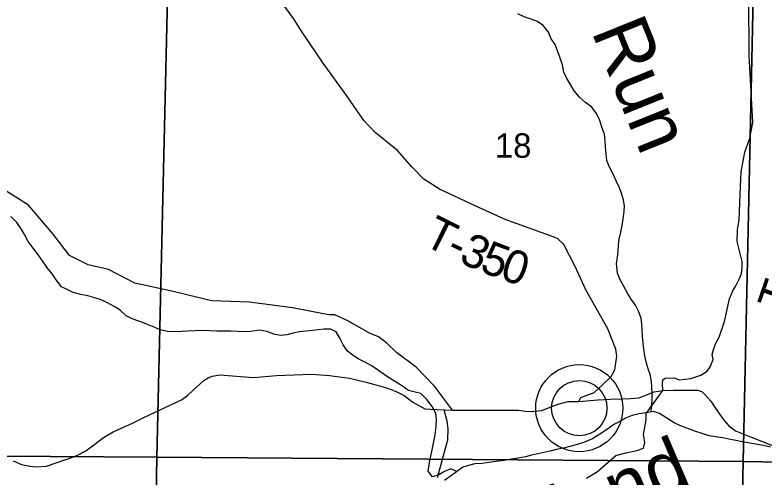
# Model space of a CAD drawing. Extents: x 0 to 34, y 0 to 22.
# Drawn here: x 3.273 to 4.552, y 18.088 to 18.878 of the extents above; entities that cross this region are included whole.
import ezdxf

# ---------------------------------------------------------------- set-up
doc = ezdxf.new("R2010")
doc.units = 0
for name, color, linetype in [('GM_X_County_Road', 7, 'Continuous'), ('GM_X_Minor_River', 7, 'Continuous'), ('GM_X_Minor_River_Text', 7, 'Continuous'), ('GM_X_Section', 7, 'Continuous'), ('GM_X_Section_Text', 7, 'Continuous'), ('GM_X_Township_Road', 7, 'Continuous'), ('GM_X_Township_Road_Text', 7, 'Continuous'), ('GM_X_Unincorporated', 7, 'Continuous'), ('GM_X_Unincorporated_Location', 7, 'Continuous')]:
    doc.layers.add(name, color=color, linetype=linetype)

msp = doc.modelspace()

# ---------------------------------------------------------------- linework, layer by layer
at = {"layer": 'GM_X_County_Road'}
for p, q in [((3.5775, 18.2366), (3.5956, 18.2532)), ((3.5956, 18.2532), (3.6027, 18.2576)), ((3.6027, 18.2576), (3.6094, 18.2609)), ((3.6094, 18.2609), (3.6226, 18.2629)), ((3.6226, 18.2629), (3.6801, 18.2585)), ((3.6801, 18.2585), (3.7197, 18.262)), ((3.7197, 18.262), (3.78, 18.2638)), ((3.78, 18.2638), (3.8103, 18.2619)), ((3.8103, 18.2619), (3.844, 18.257)), ((3.844, 18.257), (3.8725, 18.2504)), ((3.8725, 18.2504), (3.9015, 18.2423)), ((3.9015, 18.2423), (3.9152, 18.2378)), ((3.5571, 18.2203), (3.5676, 18.2275)), ((3.5676, 18.2275), (3.5775, 18.2366)), ((3.9152, 18.2378), (3.926, 18.2332)), ((3.926, 18.2332), (3.9378, 18.2276)), ((3.9378, 18.2276), (3.9522, 18.2163)), ((4.3389, 18.2238), (4.3516, 18.2287)), ((4.3516, 18.2287), (4.3644, 18.234)), ((4.3644, 18.234), (4.3793, 18.236)), ((4.3793, 18.236), (4.3975, 18.2368)), ((4.3975, 18.2368), (4.4395, 18.2365)), ((4.4395, 18.2365), (4.4464, 18.2337)), ((4.4464, 18.2337), (4.451, 18.2295)), ((4.451, 18.2295), (4.4613, 18.2179)), ((3.4943, 18.1906), (3.5571, 18.2203)), ((3.9522, 18.2163), (3.9726, 18.2051)), ((4.2007, 18.2129), (4.2178, 18.2175)), ((4.2178, 18.2175), (4.2357, 18.2174)), ((4.2357, 18.2174), (4.2681, 18.2202)), ((4.2681, 18.2202), (4.2897, 18.2213)), ((4.2897, 18.2213), (4.3089, 18.222)), ((4.3089, 18.222), (4.3239, 18.2223)), ((4.3239, 18.2223), (4.3389, 18.2238)), ((4.4613, 18.2179), (4.4735, 18.1991)), ((3.9726, 18.2051), (3.9822, 18.2041)), ((3.9822, 18.2041), (4.0058, 18.2033)), ((4.0058, 18.2033), (4.0199, 18.2026)), ((4.0199, 18.2026), (4.1326, 18.2027)), ((4.1326, 18.2027), (4.1441, 18.2008)), ((4.155, 18.2004), (4.1721, 18.2019)), ((4.1721, 18.2019), (4.2007, 18.2129)), ((3.4738, 18.1802), (3.4943, 18.1906)), ((4.1441, 18.2008), (4.155, 18.2004)), ((4.4735, 18.1991), (4.484, 18.1851)), ((3.4409, 18.1653), (3.4738, 18.1802)), ((4.484, 18.1851), (4.4919, 18.176)), ((4.4919, 18.176), (4.5034, 18.1673)), ((3.4242, 18.1561), (3.4409, 18.1653)), ((4.5034, 18.1673), (4.5292, 18.1568)), ((3.4069, 18.1429), (3.4242, 18.1561)), ((4.5292, 18.1568), (4.5694, 18.1412)), ((3.3939, 18.1333), (3.4069, 18.1429)), ((3.3731, 18.1226), (3.3795, 18.1254)), ((3.3795, 18.1254), (3.3939, 18.1333)), ((3.2697, 18.1161), (3.2843, 18.11)), ((3.3267, 18.1069), (3.3731, 18.1226)), ((3.2843, 18.11), (3.2991, 18.1066)), ((3.2991, 18.1066), (3.309, 18.1057)), ((3.309, 18.1057), (3.3267, 18.1069))]:
    msp.add_line(p, q, dxfattribs=at)
at = {"layer": 'GM_X_Minor_River'}
for p, q in [((4.1424, 18.8745), (4.1316, 18.8794)), ((4.1528, 18.871), (4.1424, 18.8745)), ((4.1651, 18.8664), (4.1528, 18.871)), ((4.1756, 18.8588), (4.1651, 18.8664)), ((4.1839, 18.8484), (4.1756, 18.8588)), ((4.1888, 18.8371), (4.1839, 18.8484)), ((4.1952, 18.827), (4.1888, 18.8371)), ((4.1993, 18.8165), (4.1952, 18.827)), ((4.2031, 18.8056), (4.1993, 18.8165)), ((4.2077, 18.7924), (4.2031, 18.8056)), ((4.21, 18.78), (4.2077, 18.7924)), ((4.2148, 18.7702), (4.21, 18.78)), ((4.2213, 18.7586), (4.2148, 18.7702)), ((4.2281, 18.7478), (4.2213, 18.7586)), ((4.2368, 18.7374), (4.2281, 18.7478)), ((4.2469, 18.7283), (4.2368, 18.7374)), ((4.2578, 18.7202), (4.2469, 18.7283)), ((4.2662, 18.7091), (4.2578, 18.7202)), ((4.2715, 18.6975), (4.2662, 18.7091)), ((4.2749, 18.6862), (4.2715, 18.6975)), ((4.2798, 18.6741), (4.2749, 18.6862)), ((4.2809, 18.6624), (4.2798, 18.6741)), ((4.2816, 18.6521), (4.2809, 18.6624)), ((4.2824, 18.6407), (4.2816, 18.6521)), ((4.2835, 18.629), (4.2824, 18.6407)), ((4.2876, 18.6185), (4.2835, 18.629)), ((4.2941, 18.6069), (4.2876, 18.6185)), ((4.2998, 18.5945), (4.2941, 18.6069)), ((4.3051, 18.5825), (4.2998, 18.5945)), ((4.3092, 18.5716), (4.3051, 18.5825)), ((4.3118, 18.5614), (4.3092, 18.5716)), ((4.3137, 18.5516), (4.3118, 18.5614)), ((4.3132, 18.542), (4.3137, 18.5516)), ((4.3117, 18.5291), (4.3132, 18.542)), ((3.2762, 18.5229), (3.2657, 18.5332)), ((3.2834, 18.5125), (3.2762, 18.5229)), ((4.3098, 18.518), (4.3117, 18.5291)), ((3.289, 18.5024), (3.2834, 18.5125)), ((4.3075, 18.5065), (4.3098, 18.518)), ((3.2955, 18.4908), (3.289, 18.5024)), ((4.3048, 18.4946), (4.3075, 18.5065)), ((3.3038, 18.4793), (3.2955, 18.4908)), ((4.3031, 18.474), (4.3036, 18.4851)), ((4.3036, 18.4851), (4.3048, 18.4946)), ((3.3129, 18.4674), (3.3038, 18.4793)), ((4.3016, 18.4633), (4.3031, 18.474)), ((3.3213, 18.4558), (3.3129, 18.4674)), ((4.3004, 18.453), (4.3016, 18.4633)), ((3.3285, 18.445), (3.3213, 18.4558)), ((3.3364, 18.4354), (3.3285, 18.445)), ((4.3017, 18.4363), (4.3004, 18.453)), ((3.3435, 18.4249), (3.3364, 18.4354)), ((4.3062, 18.425), (4.3017, 18.4363)), ((3.3523, 18.4134), (3.3435, 18.4249)), ((4.3122, 18.415), (4.3062, 18.425)), ((3.3623, 18.4084), (3.3523, 18.4134)), ((3.3723, 18.4038), (3.3623, 18.4084)), ((4.3191, 18.4022), (4.3122, 18.415)), ((3.3854, 18.4004), (3.3723, 18.4038)), ((3.3976, 18.3981), (3.3854, 18.4004)), ((3.4095, 18.3943), (3.3976, 18.3981)), ((3.4199, 18.3908), (3.4095, 18.3943)), ((4.3251, 18.3921), (4.3191, 18.4022)), ((3.4311, 18.3858), (3.4199, 18.3908)), ((3.4423, 18.3797), (3.4311, 18.3858)), ((4.3323, 18.3817), (4.3251, 18.3921)), ((4.3379, 18.3716), (4.3323, 18.3817)), ((3.4524, 18.3732), (3.4423, 18.3797)), ((3.4629, 18.3636), (3.4524, 18.3732)), ((4.3421, 18.3596), (4.3379, 18.3716)), ((3.4733, 18.3586), (3.4629, 18.3636)), ((3.4845, 18.3548), (3.4733, 18.3586)), ((3.4964, 18.3502), (3.4845, 18.3548)), ((4.3431, 18.3493), (4.3421, 18.3596)), ((3.5107, 18.3446), (3.4964, 18.3502)), ((3.5211, 18.3396), (3.5107, 18.3446)), ((4.3442, 18.3391), (4.3431, 18.3493)), ((3.5333, 18.3369), (3.5211, 18.3396)), ((3.547, 18.3362), (3.5333, 18.3369)), ((3.5584, 18.3369), (3.547, 18.3362)), ((3.5679, 18.3376), (3.5584, 18.3369)), ((3.593, 18.3384), (3.5679, 18.3376)), ((3.6055, 18.338), (3.593, 18.3384)), ((3.6177, 18.3376), (3.6055, 18.338)), ((3.6302, 18.3377), (3.6177, 18.3376)), ((3.6417, 18.3376), (3.6302, 18.3377)), ((3.6527, 18.3372), (3.6417, 18.3376)), ((3.6649, 18.3365), (3.6527, 18.3372)), ((3.6755, 18.3372), (3.6649, 18.3365)), ((3.6906, 18.3392), (3.6755, 18.3372)), ((3.7029, 18.3369), (3.6906, 18.3392)), ((3.7167, 18.332), (3.7029, 18.3369)), ((3.7267, 18.33), (3.7167, 18.332)), ((3.7373, 18.3311), (3.7267, 18.33)), ((3.7478, 18.3341), (3.7373, 18.3311)), ((3.7588, 18.3363), (3.7478, 18.3341)), ((3.7808, 18.3386), (3.7588, 18.3363)), ((3.7906, 18.34), (3.7808, 18.3386)), ((3.8005, 18.3411), (3.7906, 18.34)), ((3.8119, 18.3407), (3.8005, 18.3411)), ((3.8215, 18.3364), (3.8119, 18.3407)), ((3.8276, 18.3256), (3.8215, 18.3364)), ((4.3445, 18.3288), (4.3442, 18.3391)), ((3.8332, 18.3139), (3.8276, 18.3256)), ((4.3457, 18.3171), (4.3445, 18.3288)), ((4.3468, 18.3065), (4.3457, 18.3171)), ((3.8404, 18.3039), (3.8332, 18.3139)), ((3.8505, 18.2958), (3.8404, 18.3039)), ((4.3486, 18.2955), (4.3468, 18.3065)), ((3.8602, 18.2897), (3.8505, 18.2958)), ((4.3508, 18.2853), (4.3486, 18.2955)), ((3.8714, 18.2839), (3.8602, 18.2897)), ((3.8823, 18.2782), (3.8714, 18.2839)), ((3.8959, 18.2687), (3.8823, 18.2782)), ((4.3534, 18.2751), (4.3508, 18.2853)), ((3.9091, 18.2593), (3.8959, 18.2687)), ((4.3576, 18.2634), (4.3534, 18.2751)), ((3.9347, 18.2433), (3.9091, 18.2593)), ((4.3599, 18.2517), (4.3576, 18.2634)), ((3.9451, 18.2364), (3.9347, 18.2433)), ((4.3606, 18.2415), (4.3599, 18.2517)), ((4.3609, 18.2316), (4.3606, 18.2415)), ((3.9563, 18.2333), (3.9451, 18.2364)), ((3.9658, 18.231), (3.9563, 18.2333)), ((3.976, 18.221), (3.9658, 18.231)), ((4.3608, 18.2213), (4.3609, 18.2316)), ((3.9852, 18.2087), (3.976, 18.221)), ((4.3604, 18.2095), (4.3608, 18.2213)), ((3.9916, 18.1968), (3.9852, 18.2087)), ((4.3586, 18.1994), (4.3604, 18.2095)), ((3.9927, 18.1862), (3.9916, 18.1968)), ((4.3154, 18.1887), (4.3057, 18.1834)), ((4.3271, 18.1936), (4.3154, 18.1887)), ((4.3391, 18.1963), (4.3271, 18.1936)), ((4.3501, 18.1981), (4.3391, 18.1963)), ((4.3634, 18.2001), (4.3501, 18.1981)), ((4.3737, 18.1966), (4.3634, 18.2001)), ((4.3861, 18.189), (4.3737, 18.1966)), ((4.3986, 18.181), (4.3861, 18.189)), ((3.9919, 18.1755), (3.9927, 18.1862)), ((4.2956, 18.1778), (4.2833, 18.169)), ((4.3057, 18.1834), (4.2956, 18.1778)), ((4.4082, 18.1764), (4.3986, 18.181)), ((4.4205, 18.1718), (4.4082, 18.1764)), ((3.9891, 18.1545), (3.9911, 18.1644)), ((3.9911, 18.1644), (3.9919, 18.1755)), ((4.2833, 18.169), (4.2714, 18.1614)), ((4.4336, 18.1665), (4.4205, 18.1718)), ((4.4482, 18.162), (4.4336, 18.1665)), ((3.9868, 18.1434), (3.9891, 18.1545)), ((4.2591, 18.1534), (4.2452, 18.1477)), ((4.2714, 18.1614), (4.2591, 18.1534)), ((4.4585, 18.1589), (4.4482, 18.162)), ((4.4689, 18.157), (4.4585, 18.1589)), ((4.4815, 18.1551), (4.4689, 18.157)), ((4.4922, 18.1531), (4.4815, 18.1551)), ((4.504, 18.1508), (4.4922, 18.1531)), ((4.5148, 18.1485), (4.504, 18.1508)), ((3.9849, 18.1319), (3.9868, 18.1434)), ((4.2094, 18.1378), (4.1973, 18.1351)), ((4.2203, 18.1404), (4.2094, 18.1378)), ((4.2313, 18.1434), (4.2203, 18.1404)), ((4.2452, 18.1477), (4.2313, 18.1434)), ((4.5247, 18.1465), (4.5148, 18.1485)), ((4.5373, 18.1443), (4.5247, 18.1465)), ((4.5511, 18.142), (4.5373, 18.1443)), ((4.563, 18.1394), (4.5511, 18.142)), ((3.9825, 18.1215), (3.9849, 18.1319)), ((4.1547, 18.1254), (4.1449, 18.1228)), ((4.1656, 18.128), (4.1547, 18.1254)), ((4.186, 18.1325), (4.1656, 18.128)), ((4.1973, 18.1351), (4.186, 18.1325)), ((3.9802, 18.11), (3.9825, 18.1215)), ((4.0703, 18.1117), (4.0582, 18.1106)), ((4.0828, 18.1129), (4.0703, 18.1117)), ((4.0945, 18.1148), (4.0828, 18.1129)), ((4.1082, 18.1167), (4.0945, 18.1148)), ((4.1206, 18.119), (4.1082, 18.1167)), ((4.1324, 18.1205), (4.1206, 18.119)), ((4.1449, 18.1228), (4.1324, 18.1205)), ((3.9783, 18.0986), (3.9802, 18.11)), ((4.0174, 18.1025), (4.0065, 18.0975)), ((4.0273, 18.0976), (4.0174, 18.1025)), ((4.0378, 18.105), (4.027, 18.0974)), ((4.0476, 18.108), (4.0378, 18.105)), ((4.0582, 18.1106), (4.0476, 18.108)), ((3.9858, 18.0885), (3.9783, 18.0986)), ((3.9968, 18.0923), (3.9858, 18.0885)), ((4.0065, 18.0975), (3.9968, 18.0923)), ((4.0162, 18.0891), (4.0066, 18.0823)), ((4.027, 18.0974), (4.0162, 18.0891))]:
    msp.add_line(p, q, dxfattribs=at)
at = {"layer": 'GM_X_Section'}
for p, q in [((3.5387, 19.1524), (3.5154, 18.1224)), ((3.5154, 18.1224), (3.5387, 19.1524)), ((4.5388, 19.1444), (4.5166, 18.1148)), ((4.5166, 18.1148), (4.5388, 19.1444)), ((3.5154, 18.1224), (2.5107, 18.1291)), ((2.5107, 18.1291), (3.5154, 18.1224)), ((3.5154, 18.1224), (3.4934, 17.1171)), ((3.4934, 17.1171), (3.5154, 18.1224)), ((4.5166, 18.1148), (3.5154, 18.1224)), ((3.5154, 18.1224), (4.5166, 18.1148)), ((4.5166, 18.1148), (4.4928, 17.1099)), ((4.4928, 17.1099), (4.5166, 18.1148)), ((5.5198, 18.1024), (4.5166, 18.1148)), ((4.5166, 18.1148), (5.5198, 18.1024))]:
    msp.add_line(p, q, dxfattribs=at)
at = {"layer": 'GM_X_Township_Road'}
for p, q in [((4.5268, 18.8092), (4.5262, 18.9174)), ((3.7486, 18.8714), (3.7288, 18.8988)), ((3.7645, 18.8465), (3.7486, 18.8714)), ((3.7994, 18.7953), (3.7645, 18.8465)), ((4.5327, 18.6939), (4.5268, 18.8092)), ((3.8396, 18.7396), (3.7994, 18.7953)), ((3.8689, 18.6973), (3.8396, 18.7396)), ((3.8879, 18.6771), (3.8689, 18.6973)), ((4.5276, 18.6674), (4.5327, 18.6939)), ((3.9259, 18.6462), (3.8879, 18.6771)), ((4.5193, 18.6431), (4.5276, 18.6674)), ((3.9509, 18.618), (3.9259, 18.6462)), ((4.5132, 18.6095), (4.5193, 18.6431)), ((3.9711, 18.5969), (3.9509, 18.618)), ((4.5117, 18.5848), (4.5132, 18.6095)), ((3.998, 18.5798), (3.9711, 18.5969)), ((3.2961, 18.5526), (3.2459, 18.5838)), ((4.0586, 18.5514), (3.998, 18.5798)), ((4.511, 18.5565), (4.5117, 18.5848)), ((3.338, 18.5031), (3.2961, 18.5526)), ((4.1098, 18.528), (4.0586, 18.5514)), ((4.5096, 18.5279), (4.511, 18.5565)), ((4.1918, 18.4988), (4.1098, 18.528)), ((4.5066, 18.5113), (4.5096, 18.5279)), ((4.5062, 18.4909), (4.5066, 18.5113)), ((3.366, 18.4668), (3.338, 18.5031)), ((4.1994, 18.4957), (4.1918, 18.4988)), ((4.2099, 18.4854), (4.1994, 18.4957)), ((4.2293, 18.448), (4.2099, 18.4854)), ((4.5145, 18.4565), (4.5062, 18.4909)), ((3.3981, 18.4507), (3.366, 18.4668)), ((3.4329, 18.4427), (3.3981, 18.4507)), ((4.248, 18.4081), (4.2293, 18.448)), ((4.5137, 18.4362), (4.5145, 18.4459)), ((4.5145, 18.4459), (4.5145, 18.4565)), ((3.4778, 18.4193), (3.4329, 18.4427)), ((4.51, 18.4275), (4.5137, 18.4362)), ((3.5431, 18.4051), (3.4778, 18.4193)), ((4.5038, 18.4148), (4.51, 18.4275)), ((4.2856, 18.3417), (4.248, 18.4081)), ((4.4932, 18.3927), (4.4987, 18.4065)), ((4.4987, 18.4065), (4.5038, 18.4148)), ((3.6085, 18.3894), (3.5431, 18.4051)), ((3.6736, 18.3873), (3.6085, 18.3894)), ((3.7467, 18.3772), (3.6736, 18.3873)), ((4.4843, 18.3542), (4.4932, 18.3927)), ((3.8087, 18.3652), (3.7467, 18.3772)), ((3.819, 18.3653), (3.8087, 18.3652)), ((3.8412, 18.3549), (3.819, 18.3653)), ((3.8785, 18.3341), (3.8412, 18.3549)), ((4.4752, 18.3275), (4.4843, 18.3542)), ((3.8935, 18.3278), (3.8785, 18.3341)), ((4.2987, 18.3066), (4.2856, 18.3417)), ((3.9085, 18.3166), (3.8935, 18.3278)), ((3.9244, 18.3011), (3.9085, 18.3166)), ((4.4662, 18.3076), (4.4697, 18.3172)), ((4.4697, 18.3172), (4.4724, 18.3223)), ((4.4724, 18.3223), (4.4752, 18.3275)), ((4.3005, 18.2947), (4.2987, 18.3066)), ((4.4634, 18.2975), (4.4652, 18.3039)), ((4.4652, 18.3039), (4.4662, 18.3076)), ((3.9579, 18.2762), (3.9244, 18.3011)), ((4.2973, 18.2717), (4.3005, 18.2947)), ((4.4652, 18.2892), (4.4634, 18.2975)), ((4.4601, 18.2768), (4.4652, 18.2892)), ((3.9894, 18.2433), (3.9579, 18.2762)), ((4.2911, 18.2603), (4.2973, 18.2717)), ((4.4439, 18.2622), (4.4547, 18.2693)), ((4.4547, 18.2693), (4.4601, 18.2768)), ((4.2757, 18.2454), (4.2911, 18.2603)), ((4.3786, 18.2483), (4.3794, 18.2541)), ((4.3794, 18.2541), (4.3832, 18.2574)), ((4.3832, 18.2574), (4.398, 18.258)), ((4.398, 18.258), (4.4079, 18.2545)), ((4.4079, 18.2545), (4.4271, 18.2566)), ((4.4271, 18.2566), (4.4439, 18.2622)), ((4.0199, 18.2026), (3.9894, 18.2433)), ((4.2619, 18.2327), (4.2757, 18.2454)), ((4.3793, 18.236), (4.3786, 18.2483)), ((4.2392, 18.2242), (4.2619, 18.2327)), ((4.351, 18.1968), (4.3737, 18.2283)), ((4.3737, 18.2283), (4.3793, 18.236)), ((4.2357, 18.2174), (4.2392, 18.2242)), ((4.0058, 18.2033), (4.0199, 18.2026)), ((4.0111, 18.1837), (4.0058, 18.2033)), ((4.3506, 18.1861), (4.351, 18.1968)), ((4.0125, 18.1707), (4.0111, 18.1837)), ((4.3463, 18.1607), (4.3506, 18.1861)), ((4.0121, 18.1516), (4.0125, 18.1707)), ((3.9943, 18.0877), (4.0121, 18.1516)), ((4.3484, 18.1471), (4.3463, 18.1607)), ((4.335, 18.1337), (4.3461, 18.1378)), ((4.3461, 18.1378), (4.3484, 18.1471)), ((4.286, 18.1139), (4.2989, 18.1253)), ((4.2989, 18.1253), (4.316, 18.1297)), ((4.316, 18.1297), (4.335, 18.1337)), ((4.2675, 18.0977), (4.286, 18.1139)), ((4.249, 18.0865), (4.2675, 18.0977))]:
    msp.add_line(p, q, dxfattribs=at)
at = {"layer": 'GM_X_Unincorporated'}
for radius in [0.0744, 0.0472]:
    msp.add_circle((4.2366, 18.206), radius, dxfattribs=at)
at = {"layer": 'GM_X_Unincorporated_Location'}
msp.add_line((4.2366, 18.206), (4.2366, 18.206), dxfattribs=at)

# ---------------------------------------------------------------- texts
at = {"layer": 'GM_X_Minor_River_Text'}
for s, height, rotation, p in [('Run', 0.0947, 291.9594, (4.2566, 18.85)), ('Island', 0.09472, 23.1154, (4.1229, 17.9398))]:
    msp.add_text(s, height=height, rotation=rotation, dxfattribs=at).set_placement(p)
at = {"layer": 'GM_X_Section_Text'}
msp.add_text('18', height=0.04186, rotation=0, dxfattribs=at).set_placement((4.0926, 18.6336))
at = {"layer": 'GM_X_Township_Road_Text'}
for s, rotation, p in [('T', 333.5749, (3.9677, 18.4861)), ('3', 335.8451, (4.029, 18.4561)), ('-', 334.526, (4.0066, 18.4667)), ('5', 339.251, (4.0643, 18.4404)), ('0', 340.9478, (4.0988, 18.4274)), ('T', 71.0839, (4.5938, 18.368))]:
    msp.add_text(s, height=0.0568, rotation=rotation, dxfattribs=at).set_placement(p)

doc.saveas('drawing.dxf')
